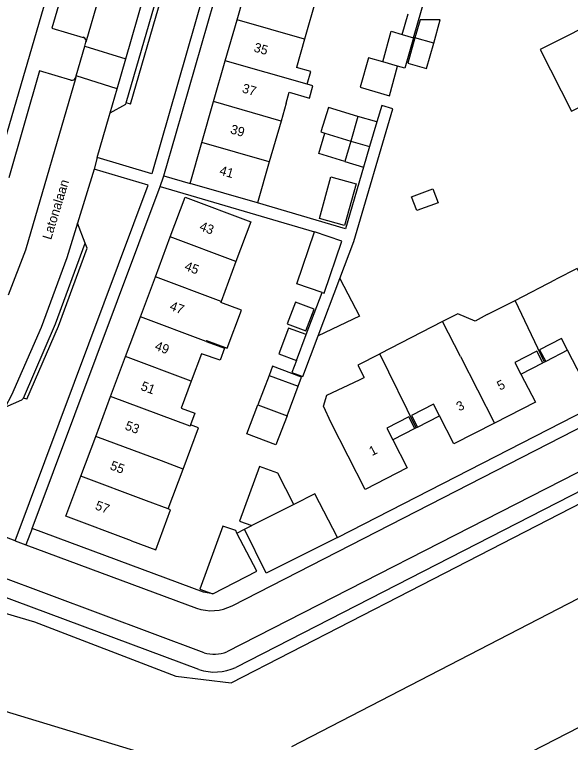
# Model space of a CAD drawing. Extents: x 194485 to 197793, y 468269 to 470822.
# Drawn here: x 196050.9 to 196122.3, y 469332.6 to 469426.1 of the extents above; entities that cross this region are included whole.
import ezdxf

# ---------------------------------------------------------------- set-up
doc = ezdxf.new("R2010")
doc.units = 0
for name, color, linetype in [('BGT begrenzing pand op maaiveld onder overbouw', 7, 'Continuous'), ('BGT grensvlak begroeid terreindeel', 7, 'Continuous'), ('BGT grensvlak gebouwinstallatie plus 1', 7, 'Continuous'), ('BGT grensvlak overig bouwwerk uitbreiding populatie', 7, 'Continuous'), ('BGT grensvlak overig bouwwerk uitbreiding populatie LR', 7, 'Continuous'), ('BGT grensvlak pand deel overbouw', 7, 'Continuous'), ('BGT grensvlak pand op maaiveld', 7, 'Continuous'), ('BGT grensvlak pand op maaiveld LR', 7, 'Continuous'), ('BGT grensvlak waterdeel', 7, 'Continuous'), ('BGT grensvlak wegdeel', 7, 'Continuous'), ('BGT tekst huisnummerreeks', 7, 'Continuous'), ('BGT tekst openbare ruimte label weg', 7, 'Continuous')]:
    doc.layers.add(name, color=color, linetype=linetype)

msp = doc.modelspace()

# ---------------------------------------------------------------- linework, layer by layer
at = {"layer": 'BGT begrenzing pand op maaiveld onder overbouw'}
for points in [[(196121.943, 469383.006), (196121.168, 469384.519), (196118.347, 469383.073), (196119.123, 469381.56)], [(196118.767, 469381.377), (196117.991, 469382.89), (196115.173, 469381.446), (196115.948, 469379.933)], [(196105.487, 469374.572), (196104.712, 469376.085), (196101.89, 469374.639), (196102.666, 469373.126)], [(196102.31, 469372.944), (196101.535, 469374.457), (196098.716, 469373.012), (196099.491, 469371.499)]]:
    msp.add_lwpolyline(points, dxfattribs=at)
at = {"layer": 'BGT grensvlak begroeid terreindeel'}
msp.add_lwpolyline([(196009.043, 469315.618), (196017.462, 469323.478), (196027.67, 469334.875), (196036.992, 469346.101), (196041.247, 469349.509), (196046.63, 469350.096), (196053.464, 469348.086), (196071.625, 469341.128), (196078.73, 469340.252), (196101.703, 469352.077), (196148.982, 469376.415)], dxfattribs=at)
at = {"layer": 'BGT grensvlak gebouwinstallatie plus 1'}
for p, q in [((196102.987, 469425.459), (196102.33, 469423.139)), ((196105.57, 469425.489), (196102.987, 469425.459)), ((196104.744, 469422.456), (196105.57, 469425.489)), ((196090.779, 469410.889), (196094.091, 469409.882)), ((196089.91, 469384.852), (196092.684, 469392.222)), ((196092.684, 469392.222), (196095.224, 469387.388)), ((196095.224, 469387.388), (196089.91, 469384.852)), ((196084.03, 469380.953), (196083.589, 469379.772)), ((196087.783, 469379.564), (196084.03, 469380.953)), ((196087.334, 469378.372), (196087.783, 469379.564))]:
    msp.add_line(p, q, dxfattribs=at)
for points in [[(196095.003, 469413.064), (196091.224, 469414.216), (196090.246, 469411.054), (196090.779, 469410.889)], [(196093.339, 469407.26), (196089.978, 469408.299), (196090.779, 469410.889)]]:
    msp.add_lwpolyline(points, dxfattribs=at)
at = {"layer": 'BGT grensvlak overig bouwwerk uitbreiding populatie'}
for p, q in [((196102.33, 469423.139), (196101.415, 469419.906)), ((196104.744, 469422.456), (196102.33, 469423.139)), ((196103.828, 469419.222), (196104.744, 469422.456)), ((196101.415, 469419.906), (196103.828, 469419.222)), ((196095.003, 469413.064), (196094.091, 469409.882)), ((196097.44, 469412.365), (196095.003, 469413.064)), ((196097.44, 469412.365), (196096.504, 469409.187)), ((196094.091, 469409.882), (196093.339, 469407.26)), ((196096.504, 469409.187), (196095.72, 469406.523)), ((196093.339, 469407.26), (196095.72, 469406.523))]:
    msp.add_line(p, q, dxfattribs=at)
msp.add_lwpolyline([(196101.894, 469402.735), (196104.65, 469403.756), (196105.311, 469401.971), (196102.555, 469400.951), (196101.894, 469402.735)], dxfattribs=at)
at = {"layer": 'BGT grensvlak overig bouwwerk uitbreiding populatie LR'}
msp.add_line((196094.091, 469409.882), (196096.504, 469409.187), dxfattribs=at)
at = {"layer": 'BGT grensvlak pand deel overbouw'}
for p, q in [((196121.943, 469383.006), (196119.123, 469381.56)), ((196115.948, 469379.933), (196118.767, 469381.377)), ((196102.666, 469373.126), (196105.487, 469374.572)), ((196102.31, 469372.944), (196099.491, 469371.499))]:
    msp.add_line(p, q, dxfattribs=at)
at = {"layer": 'BGT grensvlak pand op maaiveld'}
for p, q in [((196079.479, 469425.477), (196080.984, 469430.736)), ((196089.645, 469428.241), (196088.14, 469422.982)), ((196127.566, 469426.305), (196121.088, 469422.999)), ((196077.974, 469420.218), (196079.479, 469425.477)), ((196100.698, 469423.588), (196102.139, 469423.171)), ((196088.14, 469422.982), (196087.103, 469419.357)), ((196096.374, 469420.593), (196095.301, 469416.799)), ((196098.195, 469420.075), (196096.374, 469420.593)), ((196076.469, 469414.96), (196077.974, 469420.218)), ((196099.044, 469415.699), (196100.085, 469419.52)), ((196095.301, 469416.799), (196099.044, 469415.699)), ((196074.964, 469409.701), (196076.469, 469414.96)), ((196085.791, 469414.769), (196085.131, 469412.464)), ((196085.131, 469412.464), (196083.627, 469407.205)), ((196073.455, 469404.428), (196074.964, 469409.701)), ((196083.627, 469407.205), (196082.12, 469401.939)), ((196082.12, 469401.939), (196073.455, 469404.428)), ((196068.993, 469392.436), (196070.907, 469397.561)), ((196079.341, 469394.393), (196077.425, 469389.27)), ((196067.08, 469387.312), (196068.993, 469392.436)), ((196115.185, 469389.42), (196120.464, 469392.125)), ((196077.425, 469389.27), (196077.381, 469389.153)), ((196111.591, 469387.579), (196115.185, 469389.42)), ((196107.843, 469387.691), (196105.885, 469386.681)), ((196065.166, 469382.188), (196067.08, 469387.312)), ((196105.885, 469386.681), (196097.802, 469382.531)), ((196087.119, 469381.694), (196088.373, 469385.026)), ((196075.553, 469384.263), (196075.509, 469384.147)), ((196075.509, 469384.147), (196077.86, 469383.291)), ((196063.252, 469377.064), (196065.166, 469382.188)), ((196074.917, 469382.565), (196073.593, 469379.023)), ((196097.802, 469382.531), (196097.779, 469382.519)), ((196118.974, 469381.483), (196118.767, 469381.377)), ((196119.123, 469381.56), (196118.974, 469381.483)), ((196083.589, 469379.772), (196082.17, 469375.977)), ((196083.589, 469379.772), (196087.334, 469378.372)), ((196095.21, 469379.184), (196095.802, 469379.487)), ((196085.907, 469374.579), (196087.334, 469378.372)), ((196061.339, 469371.939), (196063.252, 469377.064)), ((196080.755, 469372.254), (196082.17, 469375.977)), ((196102.493, 469373.038), (196102.31, 469372.944)), ((196102.666, 469373.126), (196102.493, 469373.038)), ((196059.425, 469366.815), (196061.339, 469371.939)), ((196070.644, 469362.606), (196072.561, 469367.729)), ((196086.76, 469363.2), (196081.392, 469360.462)), ((196081.392, 469360.462), (196081.379, 469360.467))]:
    msp.add_line(p, q, dxfattribs=at)
for points in [[(196098.195, 469420.075), (196099.295, 469423.995), (196100.698, 469423.588)], [(196102.139, 469423.171), (196101.028, 469419.243), (196100.085, 469419.52)], [(196121.088, 469422.999), (196118.416, 469421.635), (196122.453, 469413.738), (196126.014, 469415.559)], [(196088.482, 469417.195), (196088.949, 469418.829), (196087.103, 469419.357)], [(196088.781, 469415.422), (196089.227, 469416.982), (196088.482, 469417.195)], [(196085.791, 469414.769), (196086.194, 469416.175), (196088.781, 469415.422)], [(196090.069, 469399.922), (196091.534, 469405.288), (196094.762, 469404.406), (196093.297, 469399.041), (196090.069, 469399.922)], [(196070.907, 469397.561), (196072.821, 469402.685), (196081.257, 469399.517), (196079.341, 469394.393)], [(196090.4, 469390.411), (196087.146, 469391.522), (196089.432, 469398.215)], [(196090.4, 469390.411), (196090.654, 469390.324), (196092.94, 469397.017), (196089.432, 469398.215)], [(196123.771, 469392.327), (196123.165, 469393.509), (196120.464, 469392.125)], [(196075.553, 469384.263), (196078.215, 469383.268), (196080.044, 469388.158), (196077.381, 469389.153)], [(196085.937, 469386.383), (196088.338, 469385.495), (196089.375, 469388.299), (196086.974, 469389.187), (196085.937, 469386.383)], [(196111.591, 469387.579), (196110.071, 469386.727), (196107.843, 469387.691)], [(196088.373, 469385.026), (196086.113, 469385.859), (196084.859, 469382.527), (196087.119, 469381.694)], [(196077.86, 469383.291), (196077.321, 469381.749), (196074.917, 469382.565)], [(196129.026, 469382.073), (196123.795, 469379.392), (196121.943, 469383.006)], [(196097.779, 469382.519), (196094.983, 469381.086), (196095.802, 469379.487)], [(196091.581, 469373.673), (196090.582, 469375.813), (196091.021, 469377.239), (196095.21, 469379.184)], [(196115.948, 469379.933), (196117.8, 469376.32), (196112.57, 469373.64)], [(196073.593, 469379.023), (196072.304, 469375.575), (196074.065, 469374.916), (196073.514, 469373.416)], [(196085.907, 469374.579), (196084.485, 469370.837), (196080.755, 469372.254)], [(196112.57, 469373.64), (196107.339, 469370.959), (196105.487, 469374.572)], [(196099.491, 469371.499), (196101.343, 469367.886), (196095.945, 469365.12), (196091.581, 469373.673)], [(196072.561, 469367.729), (196074.544, 469373.031), (196073.514, 469373.416)], [(196086.76, 469363.2), (196084.716, 469367.218), (196082.366, 469368.064), (196079.783, 469361.06), (196081.379, 469360.467)], [(196065.928, 469358.526), (196057.504, 469361.671), (196059.425, 469366.815)], [(196065.928, 469358.526), (196069.037, 469357.363), (196070.955, 469362.49), (196070.644, 469362.606)], [(196079.474, 469359.507), (196079.307, 469359.826), (196077.653, 469360.412), (196074.723, 469352.322), (196076.365, 469351.684)], [(196076.365, 469351.684), (196082.02, 469354.635), (196079.474, 469359.507)]]:
    msp.add_lwpolyline(points, dxfattribs=at)
at = {"layer": 'BGT grensvlak pand op maaiveld LR'}
for p, q in [((196088.14, 469422.982), (196079.479, 469425.477)), ((196088.482, 469417.195), (196077.974, 469420.218)), ((196100.085, 469419.52), (196098.195, 469420.075)), ((196085.131, 469412.464), (196076.469, 469414.96)), ((196083.627, 469407.205), (196074.964, 469409.701)), ((196079.341, 469394.393), (196070.907, 469397.561)), ((196077.425, 469389.27), (196068.993, 469392.436)), ((196118.974, 469381.483), (196115.185, 469389.42)), ((196075.509, 469384.147), (196067.08, 469387.312)), ((196108.19, 469382.184), (196105.885, 469386.681)), ((196073.593, 469379.023), (196065.166, 469382.188)), ((196102.493, 469373.038), (196097.802, 469382.531)), ((196108.19, 469382.184), (196112.57, 469373.64)), ((196073.447, 469373.235), (196063.252, 469377.064)), ((196082.17, 469375.977), (196085.907, 469374.579)), ((196073.514, 469373.416), (196073.447, 469373.235)), ((196069.761, 469368.776), (196061.339, 469371.939)), ((196072.561, 469367.729), (196069.761, 469368.776)), ((196067.845, 469363.653), (196059.425, 469366.815)), ((196070.644, 469362.606), (196067.845, 469363.653))]:
    msp.add_line(p, q, dxfattribs=at)
at = {"layer": 'BGT grensvlak waterdeel'}
msp.add_line((196086.54, 469332.07), (196167.744, 469374.162), dxfattribs=at)
for points in [[(196208.378, 469378.233), (196163.47, 469355.14), (196106.461, 469325.81)], [(196017.278, 469306.175), (196027.716, 469316.143), (196040.288, 469329.962), (196046.272, 469337.634), (196071.12, 469330.12)]]:
    msp.add_lwpolyline(points, dxfattribs=at)
at = {"layer": 'BGT grensvlak wegdeel'}
for p, q in [((196065.19, 469420.454), (196072.335, 469445.032)), ((196102.139, 469423.171), (196108.506, 469445.369)), ((196065.227, 469414.798), (196073.605, 469443.424)), ((196065.786, 469414.645), (196074.147, 469443.212)), ((196063.618, 469434.837), (196060.081, 469422.6)), ((196100.698, 469423.588), (196101.456, 469426.231)), ((196059.935, 469422.096), (196060.081, 469422.6)), ((196058.821, 469418.253), (196059.935, 469422.096)), ((196059.935, 469422.096), (196065.19, 469420.454)), ((196064.074, 469416.612), (196065.19, 469420.454)), ((196058.759, 469418.04), (196058.821, 469418.253)), ((196064.074, 469416.612), (196058.821, 469418.253)), ((196063.171, 469413.507), (196064.074, 469416.612)), ((196065.182, 469414.645), (196065.227, 469414.798)), ((196065.786, 469414.645), (196065.227, 469414.798)), ((196063.171, 469413.507), (196065.182, 469414.645)), ((196061.503, 469407.768), (196061.112, 469406.292)), ((196061.112, 469406.292), (196058.996, 469399.342)), ((196070.085, 469405.421), (196073.455, 469404.428)), ((196053.175, 469360.102), (196069.591, 469404.064)), ((196069.591, 469404.064), (196089.432, 469398.215)), ((196059.997, 469396.746), (196058.996, 469399.342)), ((196088.373, 469385.026), (196090.4, 469390.411)), ((196092.381, 469358.957), (196152.313, 469389.669)), ((196049.708, 469375.692), (196051.855, 469376.642)), ((196052.48, 469376.711), (196052.053, 469376.866)), ((196078.854, 469350.171), (196129.598, 469376.206)), ((196080.452, 469360), (196081.392, 469360.462)), ((196051, 469358.513), (196047.317, 469359.906)), ((196053.175, 469360.102), (196052.343, 469358.013)), ((196075.178, 469351.917), (196053.175, 469360.102)), ((196079.474, 469359.507), (196080.452, 469360)), ((196083.23, 469354.35), (196080.452, 469360)), ((196092.381, 469358.957), (196083.23, 469354.35)), ((196051, 469358.513), (196052.343, 469358.013)), ((196052.343, 469358.013), (196074.26, 469349.849)), ((196075.265, 469344.131), (196043.683, 469355.921)), ((196074.565, 469341.975), (196042.885, 469353.783)), ((196076.365, 469351.684), (196075.178, 469351.917))]:
    msp.add_line(p, q, dxfattribs=at)
for points in [[(196073.843, 469450.221), (196080.752, 469448.209), (196068.543, 469405.658), (196061.503, 469407.768)], [(196070.085, 469405.421), (196071.667, 469410.891), (196082.228, 469447.703)], [(196043.939, 469392.416), (196045.115, 469395.329), (196046.642, 469399.741), (196049.715, 469410.089), (196057.545, 469436.973)], [(196063.002, 469434.507), (196058.994, 469435.67), (196055.7, 469424.408), (196059.741, 469423.219)], [(196058.148, 469417.726), (196054.111, 469418.903), (196050.165, 469405.159)], [(196058.759, 469418.04), (196052.311, 469395.851), (196050.069, 469390.071)], [(196092.684, 469392.222), (196094.474, 469396.979), (196099.498, 469414.045), (196098.059, 469414.469), (196097.44, 469412.365)], [(196061.503, 469407.768), (196063.052, 469413.098), (196063.171, 469413.507)], [(196051, 469358.513), (196068.057, 469404.215), (196061.112, 469406.292)], [(196095.72, 469406.523), (196093.394, 469398.62), (196082.12, 469401.939)], [(196069.591, 469404.064), (196070.042, 469405.272), (196070.085, 469405.421)], [(196198.776, 469403.703), (196172.388, 469389.958), (196124.041, 469365.138), (196079.31, 469342.254)], [(196058.996, 469399.342), (196057.634, 469394.867), (196054.316, 469385.925), (196050.505, 469377.237), (196049.708, 469375.692)], [(196052.053, 469376.866), (196056.177, 469386.39), (196059.997, 469396.746)], [(196052.48, 469376.711), (196056.542, 469386.09), (196060.24, 469396.115), (196059.997, 469396.746)], [(196087.119, 469381.694), (196086.537, 469380.149), (196087.941, 469379.62), (196089.91, 469384.852)], [(196131.476, 469371.523), (196123.06, 469367.201), (196078.161, 469344.242)], [(196092.381, 469358.957), (196089.472, 469364.574), (196086.76, 469363.2)]]:
    msp.add_lwpolyline(points, dxfattribs=at)
for centre, radius, start, end in [((196059.587, 469422.732), 0.511, 345.05962, 72.49799), ((196058.288, 469418.205), 0.499, 253.68696, 340.71136), ((196051.44, 469377.208), 0.702, 306.224, 330.82723), ((196076.173, 469355.49), 5.956, 251.26611, 296.75266), ((196076.545, 469348.559), 4.61, 253.87389, 290.51611), ((196076.586, 469348.094), 6.444, 251.72256, 295.00753)]:
    msp.add_arc(centre, radius, start, end, dxfattribs=at)

# ---------------------------------------------------------------- texts
at = {"layer": 'BGT tekst huisnummerreeks'}
for s, rotation, p in [('35', 344, (196081.543, 469421.418)), ('37', 344, (196080.042, 469416.158)), ('39', 344, (196078.536, 469410.9)), ('41', 344, (196077.142, 469405.602)), ('43', 339.5, (196074.563, 469398.474)), ('45', 339.5, (196072.645, 469393.352)), ('47', 339.5, (196070.736, 469388.226)), ('49', 339.5, (196068.822, 469383.101)), ('5', 27.1, (196113.249, 469377.809)), ('51', 339.5, (196067.017, 469377.936)), ('3', 27.1, (196108.022, 469375.13)), ('53', 339.5, (196064.995, 469372.854)), ('1', 27.1, (196096.816, 469369.387)), ('55', 339.5, (196063.077, 469367.73)), ('57', 339.5, (196061.164, 469362.595))]:
    msp.add_text(s, height=1.2, rotation=rotation, dxfattribs=at).set_placement(p)
at = {"layer": 'BGT tekst openbare ruimte label weg'}
msp.add_text('Latonalaan', height=1.2, rotation=73, dxfattribs=at).set_placement((196055.597, 469397.127))

doc.saveas('drawing.dxf')
